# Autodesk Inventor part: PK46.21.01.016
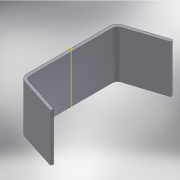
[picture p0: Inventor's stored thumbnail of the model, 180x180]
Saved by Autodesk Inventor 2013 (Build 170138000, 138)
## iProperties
Created: 2005-04
Part Number: PK46.21.01.016
Material: Steel, Mild
Document SubType Name: Листовой материал
Designer: salex
Manufacturer: Standard
Standards Organization: Custom
Density: 7.86 g/cm^3
Sheet Metal Rule: По умолчанию
Author: salex
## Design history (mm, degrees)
node "ФлнОтгиб1"
  sketch "Эскиз1"
    geometry: L1 (190.994, 220)-(35.994, 170); L2 (35.994, 170)-(35.994, -170); L3 (35.994, -170)-(190.994, -220); L4 (59.031, -92)-(59.031, 92) reference; L5 (35.994, 0)-(-34.832, 0)
    constraints: 10 end point, 2 vertical, 1 equal length, 1 midpoint, 1 perpendicular, 3 other
    dimensions: "d4" = 340 distance of L1.end L2.end; "d13" = 50 vertical distance of L3.end L2.end; "d14" = 155 horizontal distance of L2.end L3.end; "d15" = 50 vertical distance of L1.start L1.end (= d13)
node "РабПлоскость1"
body "Solid1"
feature "Плакирование1" dims "d6" = 180, "d7" = 10 (= Ширина_просечки), "d9" = 20 (= Минимальный_остаток), "d11" = 20 (= Радиус_гибки), "d12" = 10, "Толщина" = 10
feature "Изгиб1" dims "d7" = 10 (= Ширина_просечки), "d8" = 5 (= Глубина_просечки), "d9" = 20 (= Минимальный_остаток), "d10" = 20 (= Радиус_гибки), "d11" = 20 (= Радиус_гибки), "d12" = 10, "Толщина" = 10, "Зазор_стыка" = 0.01
other parameters: "Радиус_гибки" = 20, "Глубина_просечки" = 5 (= 0.5 x Толщина)
